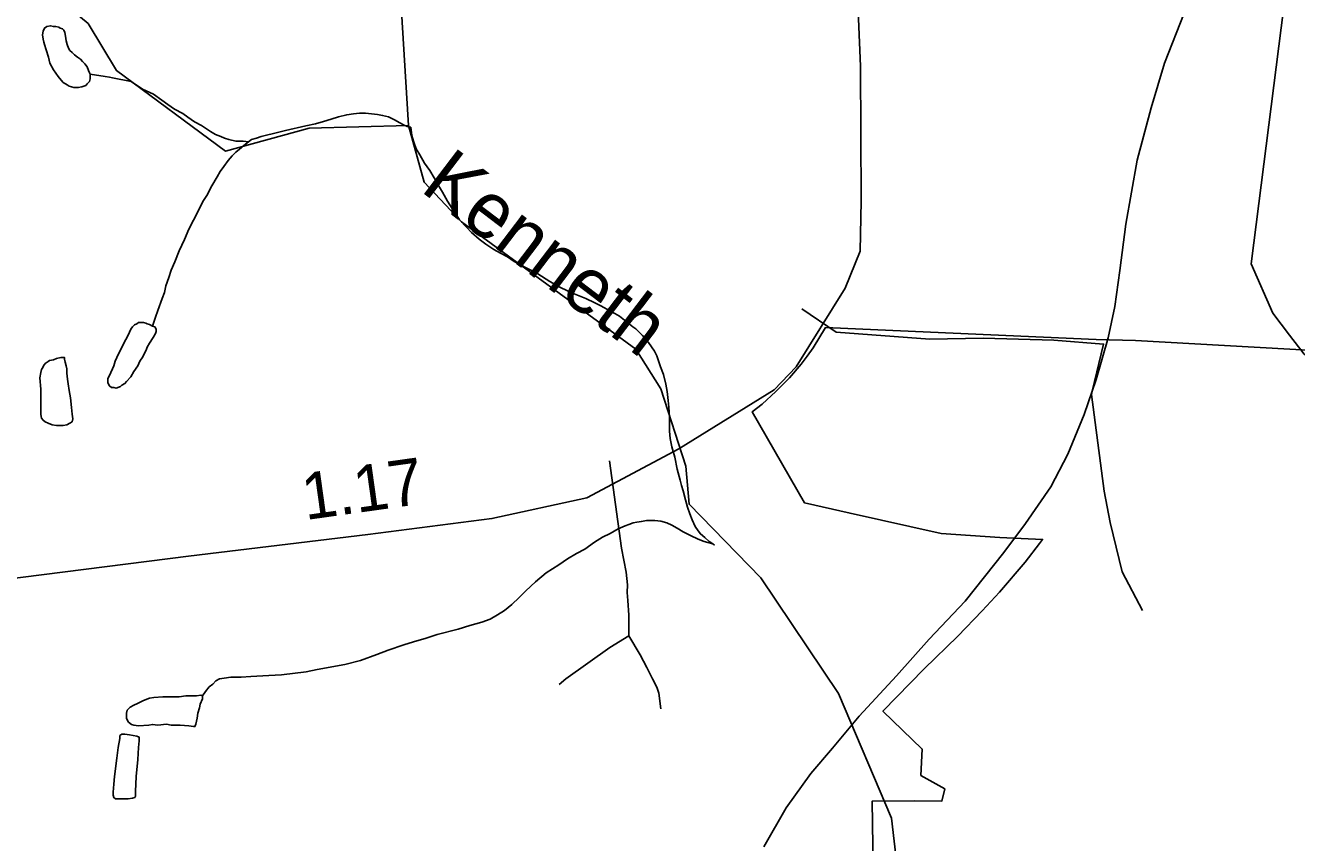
# Model space of a CAD drawing. Extents: x 2001466 to 2224147, y 644118 to 847247.
# Drawn here: x 2052246 to 2055654, y 663505 to 665696 of the extents above; entities that cross this region are included whole.
import ezdxf

# ---------------------------------------------------------------- set-up
doc = ezdxf.new("R2010")
doc.units = 0
for name, color, linetype in [('Exist Boundary Political City Limit New', 7, 'Continuous'), ('Exist Hydrographic Creek Single Shore', 7, 'Continuous'), ('Exist Hydrographic Creek Single Shore Label', 7, 'Continuous'), ('Exist Hydrographic Misc Water Feature', 7, 'Continuous'), ('Exist Railroad Mainline', 7, 'Continuous'), ('Exist Road Non-System Type 51', 7, 'Continuous'), ('Exist Road Secondary Mileage Hundredths English Label', 7, 'Continuous'), ('Exist Road Secondary Type 51 Attributed', 7, 'Continuous'), ('Map Preparation Boundary City Limit Buffer Line', 7, 'Continuous')]:
    doc.layers.add(name, color=color, linetype=linetype)

msp = doc.modelspace()

# ---------------------------------------------------------------- linework, layer by layer
at = {"layer": 'Exist Boundary Political City Limit New'}
msp.add_lwpolyline([(2055874.1, 664814.4), (2055221.9, 664851.2), (2055116.8, 664853.5), (2054451.2, 664883.7), (2054391.4, 664886.4), (2054357.5, 664831.2), (2054341.6, 664809.5), (2054325.8, 664787.8), (2054294.2, 664751.2), (2054258.2, 664714.1), (2054221.4, 664680.3), (2054194, 664659.7), (2054334.8, 664415.4), (2054457.1, 664387.9), (2054701.4, 664333.2), (2054858.4, 664322.9), (2054972.8, 664317.7), (2054964.8, 664306.6), (2054926.6, 664256.6), (2054857.8, 664176.6), (2054811.1, 664126.4), (2054746, 664058.5), (2054655.8, 663970.4), (2054545, 663857.6), (2054650.5, 663755.6), (2054646.9, 663684.9), (2054710.9, 663648.8), (2054703.1, 663616.1), (2054629.5, 663616.9), (2054516.2, 663616.1), (2054522.8, 663196.8)], dxfattribs=at)
at = {"layer": 'Exist Hydrographic Creek Single Shore'}
for points in [[(2053273.2, 665427.7), (2053006.3, 665420.1), (2052782.4, 665359), (2052490.4, 665574.9), (2052414.3, 665701.1), (2052256.4, 665832.3), (2052022.2, 665948.5), (2051756.3, 665950.7), (2051539.3, 665974.8), (2051155.3, 666107.3), (2050197.3, 666481), (2049997.3, 666488.4), (2049843.6, 666575.6)], [(2053273.2, 665427.7), (2053247.2, 665851.5), (2053197.2, 665968.7)], [(2055653.1, 661148.2), (2055614.1, 661190.6), (2055588.1, 661283), (2055396.2, 661591.9), (2055079.1, 661972.5), (2054779.1, 662263.9), (2054703.1, 662406.6), (2054568.2, 663570.7), (2054426.3, 663905), (2054217.3, 664214.3), (2054025.2, 664411.9), (2054016.2, 664513.7), (2053949.3, 664721.8), (2053882.3, 664828.1), (2053415.3, 665169), (2053315.3, 665276), (2053273.2, 665427.7)]]:
    msp.add_lwpolyline(points, dxfattribs=at)
at = {"layer": 'Exist Hydrographic Misc Water Feature'}
for points in [[(2055635.4, 664865.6), (2055590.3, 664924.6), (2055532.3, 665057.1), (2055633.2, 665852)], [(2052419.6, 665565.2), (2052417.6, 665569.2), (2052415.5, 665575.2), (2052411.6, 665585.1), (2052405.5, 665593.1), (2052399.5, 665599.1), (2052393.4, 665605.1), (2052385.4, 665611.1), (2052377.4, 665617.1), (2052371.4, 665623.1), (2052365.5, 665629.1), (2052361.4, 665635), (2052357.5, 665645), (2052355.4, 665655), (2052353.4, 665667), (2052351.3, 665677), (2052349.3, 665683), (2052345.4, 665687), (2052339.2, 665689), (2052335.3, 665691), (2052327.3, 665693), (2052321.2, 665692.9), (2052313.2, 665694.9), (2052303.4, 665692.9), (2052297.2, 665688.9), (2052293.5, 665680.9), (2052291.5, 665670.9), (2052293.5, 665658.9), (2052295.4, 665650.9), (2052297.4, 665644.9), (2052301.5, 665630.9), (2052307.5, 665610.9), (2052311.6, 665594.9), (2052321.6, 665577), (2052333.5, 665559), (2052341.5, 665549), (2052347.4, 665543), (2052357.7, 665537), (2052363.6, 665533), (2052375.7, 665529.1), (2052387.6, 665529.1), (2052397.7, 665531.1), (2052407.7, 665535.1), (2052411.6, 665539.2), (2052417.6, 665545.2), (2052419.6, 665553.2), (2052419.6, 665561.2), (2052419.6, 665565.2)], [(2052529.5, 665545.4), (2052479.5, 665555.3), (2052471.5, 665557.2), (2052459.6, 665559.2), (2052419.6, 665565.2)], [(2052529.5, 665545.4), (2052559.5, 665525.4), (2052589.6, 665511.5), (2052611.7, 665495.6), (2052627.7, 665483.6), (2052645.6, 665471.6), (2052667.7, 665459.6), (2052681.7, 665449.7), (2052699.7, 665437.7), (2052717.8, 665427.7), (2052741.8, 665411.8), (2052755.7, 665403.8), (2052769.8, 665397.9), (2052779.7, 665393.9), (2052791.8, 665389.9), (2052809.8, 665386), (2052829.7, 665386), (2052843.8, 665383.6), (2052851.9, 665390)], [(2052851.9, 665390), (2052865.8, 665394), (2052877.7, 665398.1), (2052925.7, 665410.1), (2052943.7, 665414.2), (2052997.7, 665426.3), (2053023.7, 665432.3), (2053045.6, 665438.4), (2053065.7, 665444.4), (2053085.6, 665450.5), (2053107.6, 665456.4), (2053125.6, 665458.5), (2053141.6, 665460.5), (2053157.6, 665460.5), (2053173.6, 665458.6), (2053189.6, 665456.7), (2053203.5, 665454.7), (2053219.7, 665450.7), (2053235.7, 665442.7), (2053249.7, 665434.8), (2053261.6, 665428.8), (2053269.6, 665424.8), (2053279.6, 665422.8)], [(2053279.6, 665422.8), (2053281.7, 665400.8), (2053287.6, 665382.8), (2053293.8, 665364.8), (2053303.8, 665348.9), (2053315.7, 665326.9), (2053329.8, 665306.9), (2053341.9, 665287), (2053353.8, 665266.9), (2053363.9, 665249), (2053378, 665225), (2053389.9, 665205.1), (2053400, 665191.1), (2053410, 665175.1), (2053428.1, 665155.1), (2053442.2, 665141.1), (2053462.1, 665123.2), (2053480.1, 665109.2), (2053502.1, 665095.2), (2053520.1, 665085.3), (2053538.2, 665075.3), (2053556.2, 665063.4), (2053590.3, 665045.5), (2053620.2, 665029.5), (2053652.2, 665009.6), (2053680.5, 664993.6), (2053712.5, 664977.7), (2053748.4, 664963.8), (2053772.3, 664951.8), (2053788.3, 664943.8), (2053814.4, 664929.9), (2053826.5, 664923.9), (2053838.4, 664916), (2053856.4, 664901.9), (2053874.5, 664888), (2053882.5, 664882), (2053890.5, 664874.1), (2053900.5, 664864.1), (2053916.5, 664846.1), (2053924.7, 664834.1), (2053932.7, 664822.2), (2053938.6, 664810.2), (2053948.7, 664780.1), (2053956.7, 664760.2), (2053962.8, 664734.2), (2053966.7, 664714.2), (2053968.8, 664690.2), (2053970.8, 664672.2), (2053972.9, 664644.2), (2053973.1, 664622.3), (2053973.1, 664608.3), (2053974.9, 664588.3), (2053979, 664566.3), (2053987, 664538.3), (2053993.2, 664506.3), (2054001.2, 664476.4), (2054005.3, 664462.4), (2054009.2, 664448.4), (2054015.3, 664424.3), (2054021.3, 664404.4), (2054027.4, 664386.4), (2054033.4, 664370.4), (2054041.6, 664352.4), (2054049.6, 664340.5), (2054055.5, 664332.5), (2054067.4, 664322.5), (2054079.5, 664312.5), (2054088.6, 664306), (2054093.5, 664302.5)], [(2052851.9, 665390), (2052843.8, 665383.6), (2052831.8, 665374), (2052819.7, 665363.9), (2052809.8, 665355.9), (2052800, 665345.9), (2052789.9, 665333.9), (2052777.8, 665317.9), (2052768, 665303.9), (2052760, 665289.9), (2052746.1, 665265.8), (2052732.1, 665239.8), (2052722.1, 665223.8), (2052712.2, 665203.7), (2052696.2, 665173.7), (2052684.3, 665149.7), (2052672.2, 665121.8), (2052658.3, 665091.7), (2052646.4, 665061.7), (2052636.4, 665039.7), (2052630.6, 665019.7), (2052622.6, 664997.6), (2052618.5, 664979.6), (2052612.6, 664963.6), (2052600.7, 664931.6), (2052594.7, 664913.6), (2052586.7, 664889.6)], [(2052586.7, 664889.6), (2052578.7, 664893.6), (2052572.8, 664895.6), (2052568.7, 664897.6), (2052562.7, 664899.6), (2052556.8, 664899.6), (2052548.8, 664899.6), (2052544.7, 664895.5), (2052538.8, 664893.5), (2052532.8, 664887.5), (2052528.7, 664881.5), (2052524.8, 664873.5), (2052520.7, 664863.5), (2052514.8, 664853.5), (2052512.7, 664849.5), (2052508.8, 664841.5), (2052504.9, 664833.4), (2052491, 664805.4), (2052486.9, 664795.4), (2052483, 664783.4), (2052479.1, 664775.4), (2052475, 664765.4), (2052471.1, 664757.4), (2052467, 664749.4), (2052467, 664741.4), (2052467, 664737.4), (2052471.1, 664729.4), (2052477, 664725.4), (2052483, 664725.4), (2052488.9, 664723.4), (2052501, 664727.5), (2052504.9, 664731.5), (2052512.9, 664735.5), (2052517, 664741.5), (2052528.9, 664753.5), (2052537.1, 664767.6), (2052547, 664783.6), (2052552.9, 664795.6), (2052560.9, 664807.6), (2052570.9, 664827.6), (2052572.8, 664833.6), (2052578.7, 664843.6), (2052588.8, 664859.6), (2052594.7, 664869.6), (2052596.8, 664875.6), (2052596.8, 664881.6), (2052592.7, 664887.6), (2052586.7, 664889.6)], [(2055714.9, 664790.7), (2055674.2, 664814.7), (2055635.4, 664865.6)], [(2052287.2, 664721), (2052287.2, 664709), (2052287.2, 664693), (2052287.2, 664679.1), (2052287.2, 664671.1), (2052287.4, 664661.1), (2052287.4, 664653.1), (2052289.2, 664643.1), (2052293.3, 664637.1), (2052299.3, 664633.1), (2052307.2, 664629.1), (2052317.3, 664625.2), (2052329.2, 664623.2), (2052339.2, 664623.2), (2052347.2, 664623.2), (2052357.3, 664625.2), (2052365.3, 664629.2), (2052371.2, 664633.2), (2052373.3, 664641.3), (2052371.2, 664653.3), (2052369.2, 664671.3), (2052367.1, 664697.2), (2052363.2, 664717.2), (2052361, 664735.2), (2052358.9, 664747.2), (2052357.1, 664763.2), (2052357.1, 664775.2), (2052355, 664783.2), (2052353, 664793.2), (2052350.9, 664801.2), (2052350.9, 664805.2), (2052345, 664805.2), (2052340.9, 664805.2), (2052329, 664803.1), (2052321, 664799.1), (2052310.9, 664797.1), (2052307, 664795.1), (2052299, 664789.1), (2052294.9, 664783.1), (2052293.1, 664779.1), (2052289, 664773.1), (2052286.9, 664765.1), (2052285.1, 664751.1), (2052287.2, 664721)], [(2052720.4, 663898.1), (2052728.4, 663910), (2052738.5, 663922), (2052748.5, 663930), (2052756.5, 663938.1), (2052766.4, 663944.1), (2052778.5, 663946.1), (2052796.3, 663948.2), (2052824.4, 663948.2), (2052850.4, 663950.2), (2052898.4, 663952.4), (2052932.5, 663954.4), (2052998.3, 663962.6), (2053028.4, 663968.6), (2053102.2, 663982.7), (2053144.3, 663992.8), (2053188.2, 664008.9), (2053218.3, 664020.9), (2053260.1, 664035), (2053286.2, 664043.1), (2053320.2, 664053.1), (2053350.1, 664063.2), (2053406.1, 664077.3), (2053437.9, 664087.3), (2053469.9, 664095.4), (2053492, 664103.5), (2053511.9, 664115.5), (2053530, 664127.5), (2053549.9, 664143.5), (2053570, 664161.6), (2053587.8, 664179.6), (2053613.6, 664203.6), (2053641.7, 664227.7), (2053675.8, 664249.8), (2053699.6, 664265.8), (2053723.5, 664279.9), (2053745.7, 664291.9), (2053771.5, 664310), (2053793.5, 664323.9), (2053813.6, 664334), (2053835.5, 664346), (2053853.5, 664354.1), (2053863.4, 664358.1), (2053875.5, 664362.1), (2053885.5, 664364.1), (2053897.4, 664366.1), (2053911.4, 664368.2), (2053933.3, 664368.2), (2053949.3, 664366.3), (2053965.3, 664362.3), (2053979.4, 664356.3), (2053993.4, 664348.3), (2054009.4, 664338.4), (2054029.5, 664328.4), (2054049.6, 664318.5), (2054065.6, 664312.5), (2054088.6, 664306), (2054093.5, 664302.5)], [(2052720.4, 663898.1), (2052716.5, 663900.1), (2052704.4, 663898), (2052690.5, 663898), (2052676.5, 663898), (2052658.5, 663896), (2052638.4, 663895.8), (2052614.4, 663895.8), (2052590.6, 663893.8), (2052578.5, 663891.8), (2052562.5, 663885.7), (2052546.5, 663877.8), (2052536.7, 663873.7), (2052526.7, 663867.7), (2052518.7, 663859.7), (2052516.6, 663851.7), (2052516.6, 663843.7), (2052516.6, 663837.7), (2052522.8, 663827.7), (2052530.8, 663821.7), (2052536.7, 663819.7), (2052548.8, 663817.7), (2052576.7, 663819.8), (2052586.7, 663821.8), (2052600.7, 663819.8), (2052624.7, 663821.9), (2052636.8, 663819.9), (2052648.7, 663819.9), (2052660.6, 663819.9), (2052684.5, 663818), (2052696.6, 663816), (2052700.5, 663816), (2052702.6, 663822), (2052706.7, 663838), (2052708.5, 663852), (2052712.6, 663866.1), (2052714.7, 663876.1), (2052720.4, 663890.1), (2052720.4, 663898.1)], [(2052490.8, 663731.6), (2052485, 663681.6), (2052483, 663661.6), (2052480.9, 663639.6), (2052481.1, 663631.6), (2052483.2, 663625.6), (2052487.1, 663621.7), (2052499.2, 663621.7), (2052513.1, 663621.7), (2052521.1, 663621.7), (2052533, 663623.7), (2052539.2, 663625.7), (2052541, 663629.7), (2052541, 663641.7), (2052543.1, 663681.7), (2052547, 663727.8), (2052548.8, 663759.7), (2052550.6, 663777.7), (2052550.6, 663787.7), (2052544.7, 663789.7), (2052524.8, 663793.7), (2052512.7, 663795.7), (2052504.7, 663795.7), (2052498.8, 663791.6), (2052498.8, 663783.6), (2052494.9, 663759.6), (2052490.8, 663731.6)]]:
    msp.add_lwpolyline(points, dxfattribs=at)
at = {"layer": 'Exist Railroad Mainline'}
msp.add_lwpolyline([(2055352.2, 665729.1), (2055300.2, 665594.9), (2055264.2, 665474.8), (2055226.3, 665334.8), (2055196.4, 665162.8), (2055180.5, 665038.7), (2055166.6, 664942.6), (2055148.6, 664858.6), (2055116.8, 664746.6), (2055106.1, 664715.2), (2055084.8, 664652.5), (2055040.9, 664546.6), (2054994.9, 664458.5), (2054926.9, 664360.3), (2054868.9, 664282.3), (2054765.1, 664152.2), (2054669.2, 664050.1), (2054581.2, 663952.1), (2054481.4, 663843.9), (2054409.4, 663757.8), (2054351.5, 663689.8), (2054285.4, 663597.7), (2054225.5, 663493.7)], dxfattribs=at)
at = {"layer": 'Exist Road Non-System Type 51'}
for points in [[(2054327.4, 664935.6), (2054420, 664873.6), (2054670.7, 664855.1), (2054813.8, 664857.8), (2055002.8, 664852.4), (2055136.4, 664841.6), (2055106.1, 664715.2)], [(2055106.1, 664715.2), (2055104, 664706.5), (2055137.8, 664447.2), (2055154, 664363.4), (2055186.4, 664231.1), (2055240.8, 664126.9)], [(2053811.6, 664528.1), (2053843.9, 664294.7), (2053856.5, 664229.9), (2053859.8, 664195.8), (2053859.4, 664175.8), (2053860.9, 664153.8), (2053864, 664114.5), (2053864, 664058.8)], [(2053864, 664058.8), (2053812.7, 664027.9), (2053695, 663944.3), (2053676.7, 663928.7)], [(2053864, 664058.8), (2053894.3, 664008.2), (2053911.6, 663973.9), (2053927, 663943.6), (2053938.6, 663921.3), (2053944.2, 663905.2), (2053949.4, 663863.1)]]:
    msp.add_lwpolyline(points, dxfattribs=at)
at = {"layer": 'Exist Road Secondary Type 51 Attributed'}
msp.add_lwpolyline([(2054418.6, 666634.2), (2054432.9, 666421.6), (2054466.7, 666011.7), (2054484.6, 665587.1), (2054486.7, 665225.8), (2054483.6, 665090.6), (2054443.4, 664991.3), (2054312.6, 664780.1), (2054253.4, 664718.8), (2053998, 664560.4), (2053751, 664429.4), (2053496.5, 664373.7), (2053164.1, 664331.2), (2052683.1, 664272.6), (2052013.9, 664187.6)], dxfattribs=at)
at = {"layer": 'Map Preparation Boundary City Limit Buffer Line'}
msp.add_lwpolyline([(2055874.1, 664814.4), (2055221.9, 664851.2), (2055116.8, 664853.5), (2054451.2, 664883.7), (2054391.4, 664886.4), (2054357.5, 664831.2), (2054341.6, 664809.5), (2054325.8, 664787.8), (2054294.2, 664751.2), (2054258.2, 664714.1), (2054221.4, 664680.3), (2054194, 664659.7), (2054334.8, 664415.4), (2054457.1, 664387.9), (2054701.4, 664333.2), (2054858.4, 664322.9), (2054972.8, 664317.7), (2054964.8, 664306.6), (2054926.6, 664256.6), (2054857.8, 664176.6), (2054811.1, 664126.4), (2054746, 664058.5), (2054655.8, 663970.4), (2054545, 663857.6), (2054650.5, 663755.6), (2054646.9, 663684.9), (2054710.9, 663648.8), (2054703.1, 663616.1), (2054629.5, 663616.9), (2054516.2, 663616.1), (2054522.8, 663196.8)], dxfattribs=at)

# ---------------------------------------------------------------- texts
at = {"layer": 'Exist Hydrographic Creek Single Shore Label'}
msp.add_text('Kenneth', height=150, rotation=322.733, dxfattribs=at).set_placement((2053301.4, 665254.1))
at = {"layer": 'Exist Road Secondary Mileage Hundredths English Label'}
msp.add_text('1.17', height=125, rotation=7.9713, dxfattribs=at).set_placement((2052996.6, 664369.4))

doc.saveas('drawing.dxf')
